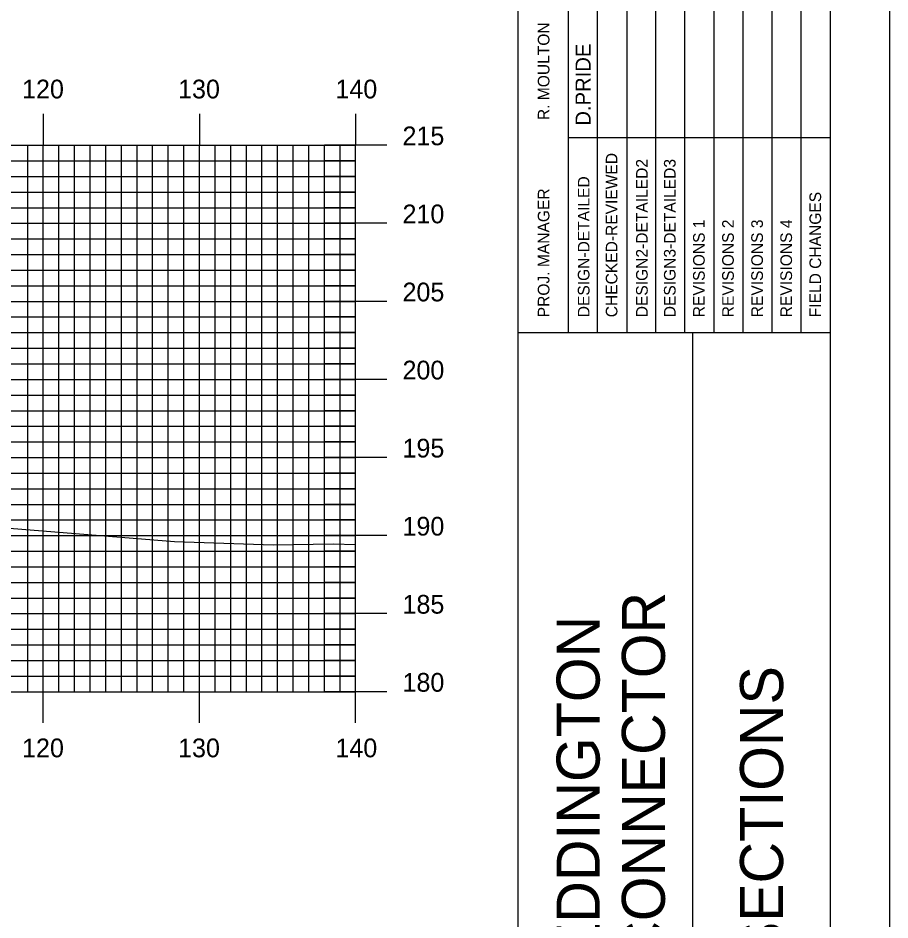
# Model space of a CAD drawing. Extents: x 1807045 to 1807388, y 442591 to 442811.
# Drawn here: x 1807329.1 to 1807385, y 442649 to 442706.8 of the extents above; entities that cross this region are included whole.
import ezdxf

# ---------------------------------------------------------------- set-up
doc = ezdxf.new("R2010")
doc.units = 0
for name, color, linetype in [('BORDER', 7, 'Continuous'), ('H_V ANNOTATION', 7, 'Continuous'), ('MAJOR', 7, 'Continuous'), ('MINOR', 7, 'Continuous'), ('PLOT BOUNDARY', 7, 'Continuous'), ('S_Roadway_Centerline', 7, 'Continuous')]:
    doc.layers.add(name, color=color, linetype=linetype)

msp = doc.modelspace()

# ---------------------------------------------------------------- linework, layer by layer
at = {"layer": 'BORDER'}
for p, q in [((1807361.159, 442596.665), (1807361.159, 442806.665)), ((1807361.159, 442686.671), (1807381.159, 442686.671)), ((1807372.341, 442616.671), (1807372.341, 442686.671))]:
    msp.add_line(p, q, dxfattribs=at)
msp.add_lwpolyline([(1807061.159, 442596.665), (1807381.159, 442596.665), (1807381.159, 442806.665), (1807061.159, 442806.665)], close=True, dxfattribs=at)
for points in [[(1807366.254, 442686.677), (1807366.254, 442721.671)], [(1807368.117, 442721.671), (1807368.117, 442686.677)], [(1807369.98, 442686.677), (1807369.98, 442721.671)], [(1807371.844, 442686.677), (1807371.844, 442721.671)], [(1807373.707, 442686.677), (1807373.707, 442721.671)], [(1807375.57, 442686.677), (1807375.57, 442721.671)], [(1807377.434, 442686.677), (1807377.434, 442721.671)], [(1807379.297, 442686.677), (1807379.297, 442721.671)], [(1807364.39, 442686.677), (1807364.39, 442720.259)], [(1807364.388, 442699.171), (1807381.159, 442699.171)]]:
    msp.add_lwpolyline(points, dxfattribs=at)
at = {"layer": 'MAJOR'}
for p, q in [((1807330.759, 442700.669), (1807330.759, 442698.665)), ((1807340.759, 442700.669), (1807340.759, 442698.665)), ((1807350.759, 442700.669), (1807350.759, 442698.665)), ((1807070.759, 442698.665), (1807350.759, 442698.665)), ((1807070.759, 442698.665), (1807350.759, 442698.665)), ((1807330.759, 442663.665), (1807330.759, 442698.665)), ((1807340.759, 442663.665), (1807340.759, 442698.665)), ((1807352.763, 442698.665), (1807348.755, 442698.665)), ((1807350.759, 442663.665), (1807350.759, 442698.665)), ((1807350.759, 442663.665), (1807350.759, 442698.665)), ((1807070.759, 442693.665), (1807350.759, 442693.665)), ((1807352.763, 442693.665), (1807348.755, 442693.665)), ((1807070.759, 442688.665), (1807350.759, 442688.665)), ((1807352.763, 442688.665), (1807348.755, 442688.665)), ((1807070.759, 442683.665), (1807350.759, 442683.665)), ((1807352.763, 442683.665), (1807348.755, 442683.665)), ((1807070.759, 442678.665), (1807350.759, 442678.665)), ((1807352.763, 442678.665), (1807348.755, 442678.665)), ((1807070.759, 442673.665), (1807350.759, 442673.665)), ((1807352.763, 442673.665), (1807348.755, 442673.665)), ((1807070.759, 442668.665), (1807350.759, 442668.665)), ((1807352.763, 442668.665), (1807348.755, 442668.665)), ((1807070.759, 442663.665), (1807350.759, 442663.665)), ((1807070.759, 442663.665), (1807350.759, 442663.665)), ((1807330.759, 442661.661), (1807330.759, 442663.665)), ((1807340.759, 442661.661), (1807340.759, 442663.665)), ((1807352.763, 442663.665), (1807348.755, 442663.665)), ((1807350.759, 442661.661), (1807350.759, 442663.665))]:
    msp.add_line(p, q, dxfattribs=at)
at = {"layer": 'MINOR'}
for p, q in [((1807329.759, 442663.665), (1807329.759, 442698.665)), ((1807331.759, 442663.665), (1807331.759, 442698.665)), ((1807332.759, 442663.665), (1807332.759, 442698.665)), ((1807333.759, 442663.665), (1807333.759, 442698.665)), ((1807334.759, 442663.665), (1807334.759, 442698.665)), ((1807335.759, 442663.665), (1807335.759, 442698.665)), ((1807336.759, 442663.665), (1807336.759, 442698.665)), ((1807337.759, 442663.665), (1807337.759, 442698.665)), ((1807338.759, 442663.665), (1807338.759, 442698.665)), ((1807339.759, 442663.665), (1807339.759, 442698.665)), ((1807341.759, 442663.665), (1807341.759, 442698.665)), ((1807342.759, 442663.665), (1807342.759, 442698.665)), ((1807343.759, 442663.665), (1807343.759, 442698.665)), ((1807344.759, 442663.665), (1807344.759, 442698.665)), ((1807345.759, 442663.665), (1807345.759, 442698.665)), ((1807346.759, 442663.665), (1807346.759, 442698.665)), ((1807347.759, 442663.665), (1807347.759, 442698.665)), ((1807348.759, 442663.665), (1807348.759, 442698.665)), ((1807349.759, 442663.665), (1807349.759, 442698.665)), ((1807070.759, 442697.665), (1807350.759, 442697.665)), ((1807350.759, 442697.665), (1807348.755, 442697.665)), ((1807070.759, 442696.665), (1807350.759, 442696.665)), ((1807350.759, 442696.665), (1807348.755, 442696.665)), ((1807070.759, 442695.665), (1807350.759, 442695.665)), ((1807350.759, 442695.665), (1807348.755, 442695.665)), ((1807070.759, 442694.665), (1807350.759, 442694.665)), ((1807350.759, 442694.665), (1807348.755, 442694.665)), ((1807070.759, 442692.665), (1807350.759, 442692.665)), ((1807350.759, 442692.665), (1807348.755, 442692.665)), ((1807070.759, 442691.665), (1807350.759, 442691.665)), ((1807350.759, 442691.665), (1807348.755, 442691.665)), ((1807070.759, 442690.665), (1807350.759, 442690.665)), ((1807350.759, 442690.665), (1807348.755, 442690.665)), ((1807070.759, 442689.665), (1807350.759, 442689.665)), ((1807350.759, 442689.665), (1807348.755, 442689.665)), ((1807070.759, 442687.665), (1807350.759, 442687.665)), ((1807350.759, 442687.665), (1807348.755, 442687.665)), ((1807070.759, 442686.665), (1807350.759, 442686.665)), ((1807350.759, 442686.665), (1807348.755, 442686.665)), ((1807070.759, 442685.665), (1807350.759, 442685.665)), ((1807350.759, 442685.665), (1807348.755, 442685.665)), ((1807070.759, 442684.665), (1807350.759, 442684.665)), ((1807350.759, 442684.665), (1807348.755, 442684.665)), ((1807070.759, 442682.665), (1807350.759, 442682.665)), ((1807350.759, 442682.665), (1807348.755, 442682.665)), ((1807070.759, 442681.665), (1807350.759, 442681.665)), ((1807350.759, 442681.665), (1807348.755, 442681.665)), ((1807070.759, 442680.665), (1807350.759, 442680.665)), ((1807350.759, 442680.665), (1807348.755, 442680.665)), ((1807070.759, 442679.665), (1807350.759, 442679.665)), ((1807350.759, 442679.665), (1807348.755, 442679.665)), ((1807070.759, 442677.665), (1807350.759, 442677.665)), ((1807350.759, 442677.665), (1807348.755, 442677.665)), ((1807070.759, 442676.665), (1807350.759, 442676.665)), ((1807350.759, 442676.665), (1807348.755, 442676.665)), ((1807070.759, 442675.665), (1807350.759, 442675.665)), ((1807350.759, 442675.665), (1807348.755, 442675.665)), ((1807070.759, 442674.665), (1807350.759, 442674.665)), ((1807350.759, 442674.665), (1807348.755, 442674.665)), ((1807070.759, 442672.665), (1807350.759, 442672.665)), ((1807350.759, 442672.665), (1807348.755, 442672.665)), ((1807070.759, 442671.665), (1807350.759, 442671.665)), ((1807350.759, 442671.665), (1807348.755, 442671.665)), ((1807070.759, 442670.665), (1807350.759, 442670.665)), ((1807350.759, 442670.665), (1807348.755, 442670.665)), ((1807070.759, 442669.665), (1807350.759, 442669.665)), ((1807350.759, 442669.665), (1807348.755, 442669.665)), ((1807070.759, 442667.665), (1807350.759, 442667.665)), ((1807350.759, 442667.665), (1807348.755, 442667.665)), ((1807070.759, 442666.665), (1807350.759, 442666.665)), ((1807350.759, 442666.665), (1807348.755, 442666.665)), ((1807070.759, 442665.665), (1807350.759, 442665.665)), ((1807350.759, 442665.665), (1807348.755, 442665.665)), ((1807070.759, 442664.665), (1807350.759, 442664.665)), ((1807350.759, 442664.665), (1807348.755, 442664.665))]:
    msp.add_line(p, q, dxfattribs=at)
at = {"layer": 'PLOT BOUNDARY'}
msp.add_lwpolyline([(1807044.972, 442590.547), (1807384.972, 442590.547), (1807384.972, 442810.547), (1807044.972, 442810.547)], close=True, dxfattribs=at)
at = {"layer": 'S_Roadway_Centerline'}
msp.add_lwpolyline([(1807259.938, 442676.383), (1807289.258, 442676.117), (1807292.175, 442676.101), (1807293.147, 442676.082), (1807293.932, 442676.046), (1807303.798, 442675.634), (1807316.087, 442675.089), (1807317.483, 442675.029), (1807339.15, 442673.287), (1807345.472, 442673.075), (1807349.323, 442673.138), (1807350.759, 442673.094)], dxfattribs=at)

# ---------------------------------------------------------------- texts
at = {"layer": 'BORDER'}
for s, height, p in [('R. MOULTON', 0.7455, (1807363.168, 442700.276)), ('D.PRIDE', 0.9691, (1807365.806, 442699.917)), ('CHECKED-REVIEWED', 0.7455, (1807367.521, 442687.647)), ('DESIGN2-DETAILED2', 0.7455, (1807369.459, 442687.647)), ('DESIGN3-DETAILED3', 0.7455, (1807371.247, 442687.647)), ('DESIGN-DETAILED', 0.7455, (1807365.732, 442687.647)), ('PROJ. MANAGER', 0.7455, (1807363.167, 442687.647)), ('FIELD CHANGES', 0.7455, (1807380.564, 442687.647)), ('REVISIONS 1', 0.7455, (1807373.111, 442687.647)), ('REVISIONS 2', 0.7455, (1807374.974, 442687.647)), ('REVISIONS 3', 0.7455, (1807376.838, 442687.647)), ('REVISIONS 4', 0.7455, (1807378.701, 442687.647)), ('1-395/ROUTE 9 CONNECTOR', 2.75575, (1807370.562, 442618.865)), ('BREWER TO EDDINGTON', 2.75575, (1807366.382, 442623.074)), ('CROSS SECTIONS', 2.75575, (1807378.128, 442632.339))]:
    msp.add_text(s, height=height, rotation=90, dxfattribs=at).set_placement(p)
at = {"layer": 'H_V ANNOTATION'}
for s, p in [('120', (1807329.399, 442701.665)), ('130', (1807339.389, 442701.665)), ('140', (1807349.464, 442701.665)), ('215', (1807353.759, 442698.665)), ('210', (1807353.759, 442693.665)), ('205', (1807353.759, 442688.665)), ('200', (1807353.759, 442683.665)), ('195', (1807353.759, 442678.665)), ('190', (1807353.759, 442673.665)), ('185', (1807353.759, 442668.665)), ('180', (1807353.759, 442663.665)), ('120', (1807329.399, 442659.465)), ('130', (1807339.389, 442659.465)), ('140', (1807349.464, 442659.465))]:
    msp.add_text(s, height=1.2, dxfattribs=at).set_placement(p)

doc.saveas('drawing.dxf')
